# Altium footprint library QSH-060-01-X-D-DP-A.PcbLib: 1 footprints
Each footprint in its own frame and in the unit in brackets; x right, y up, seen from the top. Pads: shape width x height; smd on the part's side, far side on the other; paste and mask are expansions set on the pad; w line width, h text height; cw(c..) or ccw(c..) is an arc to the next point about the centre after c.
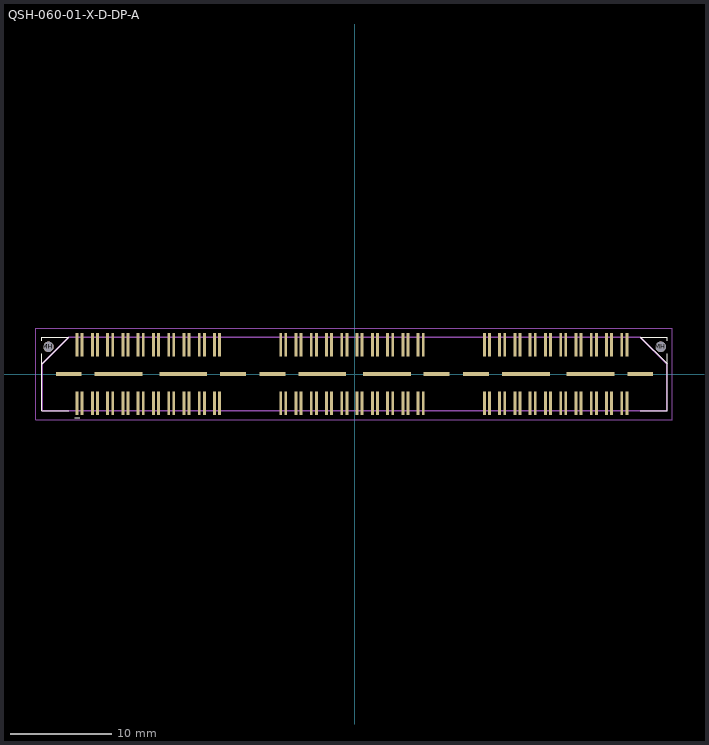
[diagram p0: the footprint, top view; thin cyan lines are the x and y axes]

## QSH-060-01-X-D-DP-A [mm]
pads (134):
  rect 2.54x0.43 smd: 0(-28.06,0) 0(-11.93,0) 0(-8.06,0) 0(8.07,0) 0(11.94,0) 0(28.07,0)
  rect 4.7x0.43 smd: 0(-23.17,0) 0(-16.82,0) 0(-3.17,0) 0(3.18,0) 0(16.83,0) 0(23.18,0)
  rect 0.28x2.27 smd: 1(-27.25,-2.87) 2(-27.25,2.87) 3(-26.75,-2.87) 4(-26.75,2.87) 5(-25.75,-2.87) 6(-25.75,2.87) 7(-25.25,-2.87) 8(-25.25,2.87) 9(-24.25,-2.87) 10(-24.25,2.87) 11(-23.75,-2.87) 12(-23.75,2.87) 13(-22.75,-2.87) 14(-22.75,2.87) 15(-22.25,-2.87) 16(-22.25,2.87) 17(-21.25,-2.87) 18(-21.25,2.87) 19(-20.75,-2.87) 20(-20.75,2.87) 21(-19.75,-2.87) 22(-19.75,2.87) 23(-19.25,-2.87) 24(-19.25,2.87) 25(-18.25,-2.87) 26(-18.25,2.87) 27(-17.75,-2.87) 28(-17.75,2.87) 29(-16.75,-2.87) 30(-16.75,2.87) 31(-16.25,-2.87) 32(-16.25,2.87) 33(-15.25,-2.87) 34(-15.25,2.87) 35(-14.75,-2.87) 36(-14.75,2.87) 37(-13.75,-2.87) 38(-13.75,2.87) 39(-13.25,-2.87) 40(-13.25,2.87) 41(-7.25,-2.87) 42(-7.25,2.87) 43(-6.75,-2.87) 44(-6.75,2.87) 45(-5.75,-2.87) 46(-5.75,2.87) 47(-5.25,-2.87) 48(-5.25,2.87) 49(-4.25,-2.87) 50(-4.25,2.87) 51(-3.75,-2.87) 52(-3.75,2.87) 53(-2.75,-2.87) 54(-2.75,2.87) 55(-2.25,-2.87) 56(-2.25,2.87) 57(-1.25,-2.87) 58(-1.25,2.87) 59(-0.75,-2.87) 60(-0.75,2.87) 61(0.25,-2.87) 62(0.25,2.87) 63(0.75,-2.87) 64(0.75,2.87) 65(1.75,-2.87) 66(1.75,2.87) 67(2.25,-2.87) 68(2.25,2.87) 69(3.25,-2.87) 70(3.25,2.87) 71(3.75,-2.87) 72(3.75,2.87) 73(4.75,-2.87) 74(4.75,2.87) 75(5.25,-2.87) 76(5.25,2.87) 77(6.25,-2.87) 78(6.25,2.87) 79(6.75,-2.87) 80(6.75,2.87) 81(12.75,-2.87) 82(12.75,2.87) 83(13.25,-2.87) 84(13.25,2.87) 85(14.25,-2.87) 86(14.25,2.87) 87(14.75,-2.87) 88(14.75,2.87) 89(15.75,-2.87) 90(15.75,2.87) 91(16.25,-2.87) 92(16.25,2.87) 93(17.25,-2.87) 94(17.25,2.87) 95(17.75,-2.87) 96(17.75,2.87) 97(18.75,-2.87) 98(18.75,2.87) 99(19.25,-2.87) 100(19.25,2.87) 101(20.25,-2.87) 102(20.25,2.87) 103(20.75,-2.87) 104(20.75,2.87) 105(21.75,-2.87) 106(21.75,2.87) 107(22.25,-2.87) 108(22.25,2.87) 109(23.25,-2.87) 110(23.25,2.87) 111(23.75,-2.87) 112(23.75,2.87) 113(24.75,-2.87) 114(24.75,2.87) 115(25.25,-2.87) 116(25.25,2.87) 117(26.25,-2.87) 118(26.25,2.87) 119(26.75,-2.87) 120(26.75,2.87)
  round 1.02 hole 1.02 unplated paste-2539.97: MH(-30.06,2.67) MH(30.07,2.67)
Top Overlay:
  lines w0.12: -30.709,2 -30.709,-3.62 -28.06,-3.62 ; -30.709,3.25 -30.709,3.62 -28.06,3.62 -30.699,0.981 ; -27.5,-4.3 -27,-4.3 ; 28.07,-3.62 30.709,-3.62 30.709,2 ; 30.691,0.999 28.07,3.62 30.709,3.62 30.709,3.25
Mechanical 15:
  lines w0.1: -31.3,-4.5 31.2,-4.5 31.2,4.5 -31.3,4.5 -31.3,-4.5
Mechanical 29:
  lines w0.127: -30.69,-3.62 -30.69,0.984 -28.054,3.62 28.079,3.62 30.69,1.009 30.69,-3.62 -30.69,-3.62
  text ".Designator" at -3.8,-0.6 h1.27
3D body "QSH-060-01-L-D-DP-A.stp": height 3.25, standoff -0.75, extent -30.64,-3.744 30.74,3.75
